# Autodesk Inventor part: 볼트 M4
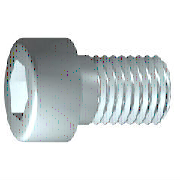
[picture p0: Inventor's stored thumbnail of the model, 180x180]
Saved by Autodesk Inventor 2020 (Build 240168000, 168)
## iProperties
Created: 2012-02
Part Number: 볼트 M4
Material: 스테인리스강
Description: 6각 소켓 머리 캡 나사
Document SubType Name: Modeling
Standard: ISO 4762
Designer: mduedu
Standard Revision: Fourth edition 2004-03-01
Standards Organization: ISO
Language: ko-KR
Size Designation: M4 x 10
Categories: <MemberInstance><Categories><Category DisplayName="조임쇠" InternalName="e4da775c-781d-43d5-af7c-5136215cf5a6" Mnemonic="FSTN"><Category DisplayName="볼트" InternalN
Density: 8.08 g/cm^3
Appearance: 반광택
IsCustomPart: 0
Author: mduedu
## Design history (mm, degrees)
sketch "스케치1"
  geometry: L1 (-1, 0)-(10, 0); L2 (10, 0)-(10, 2); L3 (10, 2)-(1.75, 2); L4 (1.75, 2)-(1.32, 2); L5 (1.32, 2)-(0, 2); L6 (0, 2)-(0, 3.5); L7 (0, 3.5)-(-4, 3.5); L8 (-4, 3.5)-(-4, 1.732); L9 (-4, 1.732)-(-2, 1.732); L10 (-2, 1.732)-(-1, 0); L11 (-6.8, 0)-(12.8, 0) reference; L12 (0, -0.7)-(0, 4.2) reference; L13 (1.75, 2)-(0, 2)
  constraints: 22 end point, 6 parallel, 2 collinear, 2 perpendicular, 1 horizontal, 1 point on line
  dimensions: "d1" = 8.25 distance from line of L3.end L2 (= GEL); "d2" = 0.42952 distance of L4.end L3.end (computed from GAL); "d3" = 4 distance between parallel lines of L8 L6 (= KOH); "d4" = 2 distance of L8.end L9.end (= INTI); "d5" = 60 deg angle of L10 L1; "d6" = 4 diameter of L3 L1 (= GD); "d7" = 4 diameter of L5 L1 (= BDM); "d8" = 3.4641 diameter of L9 L1 (= 1.1547 x SW); "d9" = 7 diameter of L7 L1 (= KOD); "d26" = 10 distance between parallel lines of L12 L2 (= NLG)
revolve "본체" sketch "스케치1" stored, may be unused: angle "d10" = 90 deg
sketch "스케치2"
  geometry: L1 (0, -4.9)-(0, 4.9) reference; L2 (-4.9, 0)-(4.9, 0) reference; L3 (1.732, 0)-(0.866, -1.5); L4 (0.866, -1.5)-(-0.866, -1.5); L5 (-0.866, -1.5)-(-1.732, 0); L6 (-1.732, 0)-(-0.866, 1.5); L7 (-0.866, 1.5)-(0.866, 1.5); L8 (0.866, 1.5)-(1.732, 0); 2 further points
  constraints: 12 end point, 1 coincident, 1 horizontal alignment, 1 point on line, 12 other
extrude "슬롯" join sketch "스케치2" stored distance "d11" = 10; taper "d12" = 0 deg
workplane "Work Plane1"
fillet "Fillet2" dims "d30" = 0.1 (= R)
body "Solid1"
fillet "모깎기1" dims "d17" = 0.4 (= RR)
feature "스레드" dims "d13" = 8.25 (= GEL), "d14" = 0
chamfer "모따기1" distance "d15" = 0.42941 (= -0.5 x SPD + 0.5 x GD); stored, may be unused: second distance "d16" = 0.42941 (= GUL), angle "d27" = 45 deg
other parameters: "GD" = 4 [user parameter; used in 2 equation terms], "NLG" = 10 [user parameter; used in 1 equation term], "GEL" = 8.25 [user parameter; used in 2 equation terms], "KOD" = 7 [user parameter; used in 1 equation term], "KOH" = 4 [user parameter; used in 1 equation term], "INTI" = 2 [user parameter; used in 1 equation term], "GAL" = 0.42941 (= 0.61345 x PTC) [user parameter; used in 1 equation term], "GUL" = 0.42941 (= 0.61345 x PTC) [user parameter; used in 1 equation term], "BDM" = 4 (= NND) [user parameter; used in 1 equation term], "SW" = 3 [user parameter; used in 2 equation terms], "RR" = 0.4 [user parameter; used in 1 equation term], "SPD" = 3.14117 (= NND - 1.2269 x PTC) [user parameter; used in 1 equation term], "d19" = 0, "d28" = 0, "d29" = 0, "R" = 0.1 [user parameter; used in 1 equation term], "TOA" = 30 deg [user parameter], "GD1" = 3.14117 (= THREADDIA - 1.2269 x PTC) [user parameter], "THREADDIA" = 4 [user parameter; used in 1 equation term], "FAWI" = 45 deg [user parameter], "TPU" = 14.28571 (computed from PTC) [user parameter], "PTC" = 0.7 [user parameter; used in 5 equation terms], "NND" = 4 [user parameter; used in 2 equation terms], "E0" = 3.465 (= 1.155 x SW) [user parameter]
